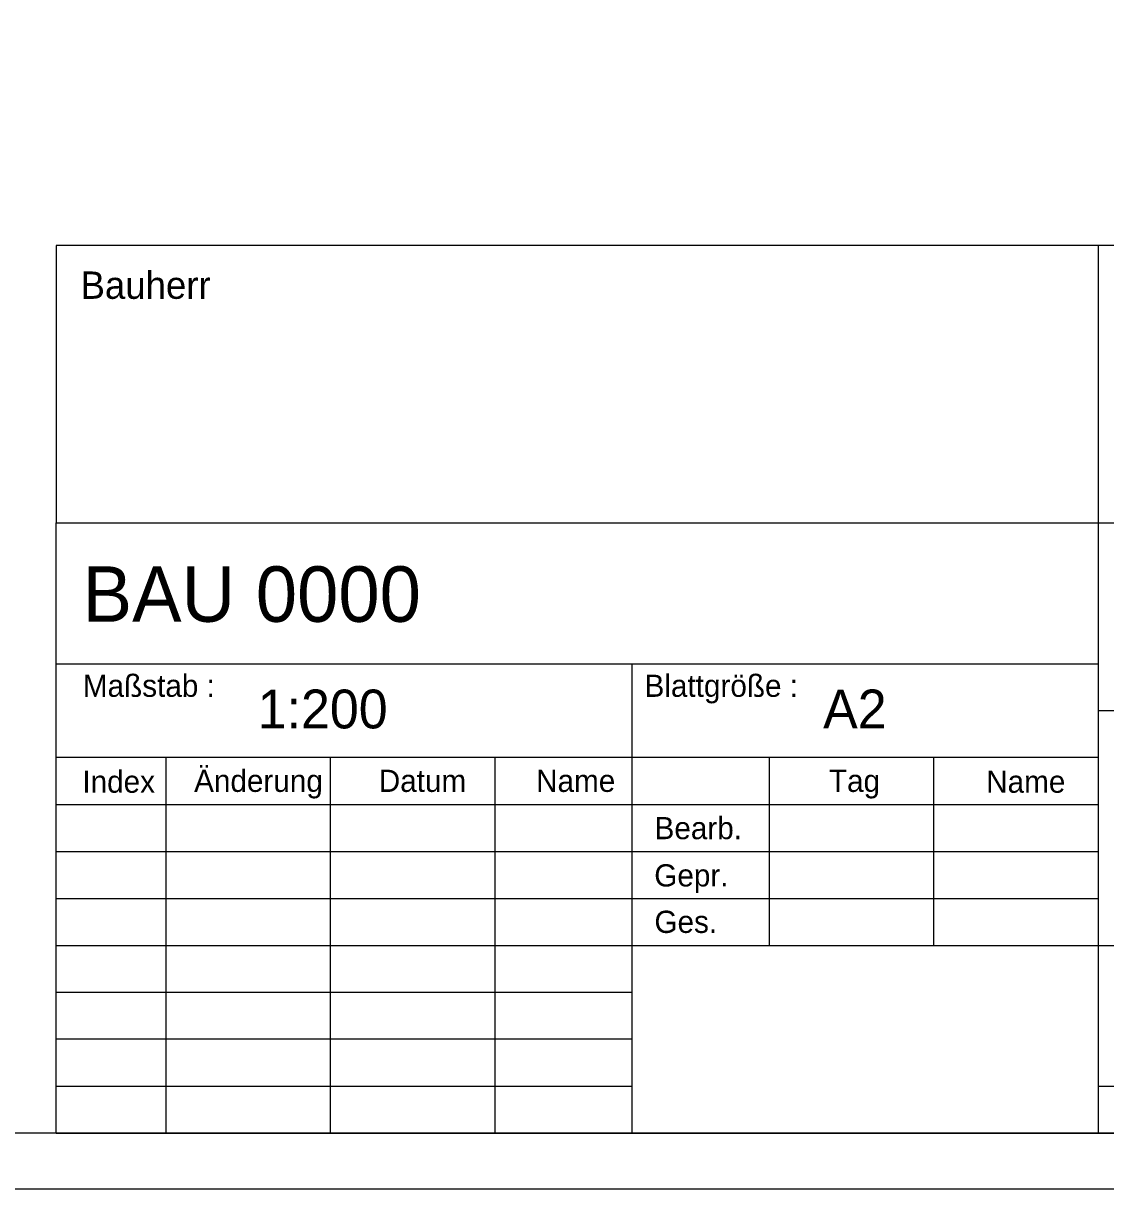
# Model space of a CAD drawing. Extents: x 0 to 119, y 0 to 84.
# Drawn here: x 81.63 to 101.13, y 0 to 21 of the extents above; entities that cross this region are included whole.
import ezdxf

# ---------------------------------------------------------------- set-up
doc = ezdxf.new("R2010")
doc.units = 0
doc.layers.add('90_Plankopf', color=7, linetype='Continuous')

msp = doc.modelspace()

# ---------------------------------------------------------------- linework, layer by layer
at = {"layer": '90_Plankopf'}
for p, q in [((117.8, 16.998), (82.224, 16.998)), ((82.224, 16.998), (82.224, 11.998)), ((101, 11.998), (101, 16.998)), ((82.224, 11.998), (117.8, 11.998)), ((82.224, 1), (82.224, 11.998)), ((82.224, 11.998), (117.8, 11.998)), ((101, 1), (101, 11.998)), ((82.224, 9.46), (101, 9.46)), ((92.6, 1), (92.6, 9.46)), ((101, 8.614), (117.8, 8.614)), ((82.224, 7.774), (101, 7.774)), ((84.2, 7.768), (84.2, 1)), ((87.165, 1), (87.165, 7.768)), ((90.13, 1), (90.13, 7.768)), ((95.071, 7.768), (95.071, 4.384)), ((98.036, 4.384), (98.036, 7.768)), ((82.224, 6.926), (101, 6.926)), ((82.224, 6.076), (101, 6.076)), ((82.224, 5.23), (101, 5.23)), ((82.224, 4.384), (101, 4.384)), ((82.224, 4.384), (101, 4.384)), ((92.6, 4.384), (101, 4.384)), ((101, 4.384), (117.8, 4.384)), ((92.6, 3.538), (82.224, 3.538)), ((92.6, 2.692), (82.224, 2.692)), ((82.224, 1.846), (92.6, 1.846)), ((101, 1.846), (117.8, 1.846)), ((117.8, 1), (82.224, 1)), ((82.224, 1), (92.6, 1)), ((84.56, 1), (117.8, 1)), ((84.56, 1), (117.8, 1))]:
    msp.add_line(p, q, dxfattribs=at)
for points in [[(0, 0), (118.8, 0), (118.8, 84), (0, 84)], [(5, 83), (117.8, 83), (117.8, 1), (5, 1)]]:
    msp.add_lwpolyline(points, close=True, dxfattribs=at)

# ---------------------------------------------------------------- texts
for s, height, p in [('Bauherr', 0.4927, (82.661, 16.035)), ('BAU 0000      ', 1, (82.698, 10.215)), ('Maßstab :', 0.4, (82.703, 8.863)), ('Blattgröße :', 0.39998, (92.823, 8.863)), ('1:200    ', 0.7, (85.852, 8.294)), ('A2       ', 0.7, (96.04, 8.294)), ('Änderung', 0.4, (84.707, 7.15)), ('Index', 0.4, (82.694, 7.135)), ('Datum', 0.4, (88.034, 7.15)), ('Name', 0.4, (90.869, 7.15)), ('Tag', 0.4, (96.145, 7.15)), ('Name', 0.4, (98.978, 7.135)), ('Bearb.', 0.4, (93.003, 6.298)), ('Gepr.', 0.4, (92.998, 5.446)), ('Ges.', 0.4, (93.001, 4.609))]:
    msp.add_text(s, height=height, dxfattribs=at).set_placement(p)

doc.saveas('drawing.dxf')
